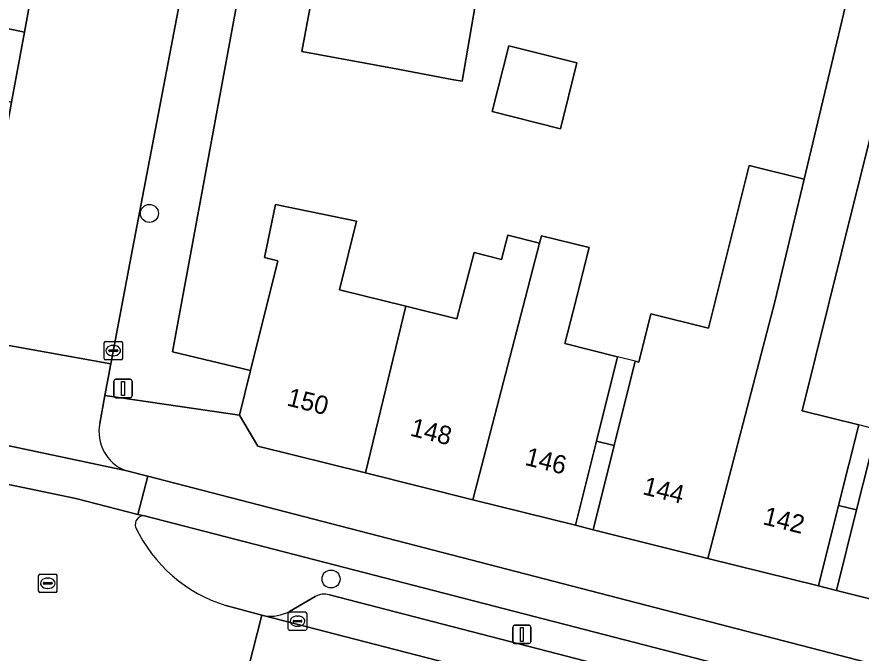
# Model space of a CAD drawing. Extents: x 158086 to 159499, y 382904 to 383981.
# Drawn here: x 158551.81 to 158597.73, y 383159.46 to 383194.06 of the extents above; entities that cross this region are included whole.
import ezdxf

# ---------------------------------------------------------------- set-up
doc = ezdxf.new("R2010")
doc.units = 0
for name, color, linetype in [('IMGEO_Berm_open', 7, 'Continuous'), ('IMGEO_Boom', 7, 'Continuous'), ('IMGEO_Erf', 7, 'Continuous'), ('IMGEO_Fietspad_gesloten', 7, 'Continuous'), ('IMGEO_Fietspad_open', 7, 'Continuous'), ('IMGEO_Kolk', 7, 'Continuous'), ('IMGEO_Lichtmast', 7, 'Continuous'), ('IMGEO_Pand', 7, 'Continuous'), ('IMGEO_Pand_nummerreeks', 7, 'Continuous'), ('IMGEO_Pand_overbouw', 7, 'Continuous'), ('IMGEO_Parkeervlak_open', 7, 'Continuous'), ('IMGEO_Rijbaan_lokaal_gesloten', 7, 'Continuous'), ('IMGEO_Rijbaan_lokaal_open', 7, 'Continuous'), ('IMGEO_Rioolput', 7, 'Continuous'), ('IMGEO_Voetpad_open', 7, 'Continuous')]:
    doc.layers.add(name, color=color, linetype=linetype)

msp = doc.modelspace()

# ---------------------------------------------------------------- linework, layer by layer
at = {"layer": 'IMGEO_Berm_open'}
for points in [[(158568.805, 383162.636), (158600.755, 383154.37), (158601.134, 383155.975), (158558.744, 383166.932)], [(158566.642, 383161.727), (158568.037, 383162.537)], [(158563.175, 383162.055), (158565.129, 383161.526), (158565.27, 383161.488)]]:
    msp.add_lwpolyline(points, dxfattribs=at)
for centre, radius, start, end in [((158558.725, 383166.449), 0.484, 87.7765, 196.6779), ((158565.51, 383169.715), 8.008, 205.1629, 253.0474), ((158568.547, 383161.605), 1.062, 75.9745, 118.7161), ((158565.576, 383163.786), 2.319, 262.406, 297.3573)]:
    msp.add_arc(centre, radius, start, end, dxfattribs=at)
at = {"layer": 'IMGEO_Boom'}
for centre in [(158559.016, 383183.371), (158568.892, 383163.49)]:
    msp.add_circle(centre, 0.489, dxfattribs=at)
at = {"layer": 'IMGEO_Erf'}
for points in [[(158565.715, 383205.279), (158560.261, 383175.849), (158564.517, 383174.829), (158566.003, 383180.788), (158565.282, 383180.967), (158565.879, 383183.857), (158570.287, 383182.948), (158569.357, 383179.223), (158572.966, 383178.323), (158575.735, 383177.632), (158576.678, 383181.236), (158578.166, 383180.867), (158578.51, 383182.182), (158580.241, 383181.753), (158580.345, 383182.152), (158582.934, 383181.511), (158582.355, 383179.223), (158582.203, 383178.621), (158581.614, 383176.29), (158584.473, 383175.577), (158583.33, 383170.993), (158582.186, 383166.409), (158583.156, 383166.167), (158584.3, 383170.751), (158585.442, 383175.335), (158585.64, 383175.286), (158586.293, 383177.907), (158589.424, 383177.127), (158591.631, 383185.974), (158594.621, 383185.228), (158598.078, 383199.698)], [(158577.248, 383197.653), (158576.03, 383190.554), (158575.573, 383190.639), (158572.23, 383191.259), (158567.313, 383192.172), (158569.64, 383204.723)], [(158598.475, 383188.502), (158597.409, 383184.23), (158594.518, 383172.64), (158597.596, 383171.872), (158596.503, 383167.492), (158595.411, 383163.111), (158596.391, 383162.867), (158597.483, 383167.248), (158598.575, 383171.628)]]:
    msp.add_lwpolyline(points, dxfattribs=at)
msp.add_lwpolyline([(158582.265, 383191.561), (158581.367, 383187.978), (158577.664, 383188.906), (158578.562, 383192.489)], close=True, dxfattribs=at)
at = {"layer": 'IMGEO_Fietspad_gesloten'}
msp.add_lwpolyline([(158606.029, 383156.879), (158558.933, 383169.076), (158558.379, 383167.006), (158558.744, 383166.932), (158601.134, 383155.975), (158606.023, 383154.711)], dxfattribs=at)
at = {"layer": 'IMGEO_Fietspad_open'}
msp.add_lwpolyline([(158544.263, 383172.235), (158543.819, 383170.193), (158543.946, 383170.167), (158555.02, 383167.876), (158558.379, 383167.006), (158558.933, 383169.076), (158557.705, 383169.396)], close=True, dxfattribs=at)
at = {"layer": 'IMGEO_Kolk'}
for p, q in [((158556.545, 383175.482), (158556.545, 383176.334)), ((158556.62, 383176.408), (158557.472, 383176.408)), ((158557.033, 383176.188), (158557.058, 383176.188)), ((158557.546, 383176.334), (158557.546, 383175.482)), ((158556.804, 383175.902), (158556.804, 383175.914)), ((158557.242, 383175.865), (158556.844, 383175.865)), ((158556.847, 383175.951), (158557.245, 383175.951)), ((158557.056, 383175.628), (158557.031, 383175.628)), ((158557.288, 383175.914), (158557.288, 383175.902)), ((158557.472, 383175.408), (158556.62, 383175.408)), ((158566.57, 383160.771), (158566.57, 383161.623)), ((158566.645, 383161.697), (158567.497, 383161.697)), ((158567.058, 383161.477), (158567.083, 383161.477)), ((158567.571, 383161.623), (158567.571, 383160.771)), ((158566.829, 383161.191), (158566.829, 383161.203)), ((158567.267, 383161.154), (158566.869, 383161.154)), ((158566.872, 383161.24), (158567.27, 383161.24)), ((158567.081, 383160.917), (158567.056, 383160.917)), ((158567.313, 383161.203), (158567.313, 383161.191)), ((158567.497, 383160.697), (158566.645, 383160.697))]:
    msp.add_line(p, q, dxfattribs=at)
for points in [[(158556.545, 383175.482), (158556.545, 383176.334)], [(158556.62, 383176.408), (158557.472, 383176.408)], [(158557.546, 383176.334), (158557.546, 383175.482)], [(158557.472, 383175.408), (158556.62, 383175.408)], [(158566.57, 383160.771), (158566.57, 383161.623)], [(158566.645, 383161.697), (158567.497, 383161.697)], [(158567.571, 383161.623), (158567.571, 383160.771)], [(158567.497, 383160.697), (158566.645, 383160.697)]]:
    msp.add_lwpolyline(points, dxfattribs=at)
for centre, radius, start, end in [((158556.622, 383176.332), 0.0765, 91.552, 178.448), ((158556.622, 383176.332), 0.0765, 91.552, 178.448), ((158557.47, 383176.332), 0.0765, 1.552, 88.448), ((158557.47, 383176.332), 0.0765, 1.552, 88.448), ((158556.844, 383175.911), 0.0403, 85.8775, 175.7526), ((158556.841, 383175.901), 0.0366, 178.938, 274.7102), ((158557.245, 383175.908), 0.043, 264.8664, 352.4533), ((158557.249, 383175.913), 0.0386, 1.7309, 96.639), ((158556.622, 383175.484), 0.0765, 181.552, 268.448), ((158556.622, 383175.484), 0.0765, 181.552, 268.448), ((158557.47, 383175.484), 0.0765, 271.552, 358.448), ((158557.47, 383175.484), 0.0765, 271.552, 358.448), ((158566.647, 383161.621), 0.0765, 91.552, 178.448), ((158566.647, 383161.621), 0.0765, 91.552, 178.448), ((158567.495, 383161.621), 0.0765, 1.552, 88.448), ((158567.495, 383161.621), 0.0765, 1.552, 88.448), ((158566.869, 383161.2), 0.0403, 85.8775, 175.7526), ((158566.866, 383161.19), 0.0366, 178.938, 274.7102), ((158567.27, 383161.197), 0.043, 264.8664, 352.4533), ((158567.274, 383161.202), 0.0386, 1.7309, 96.639), ((158566.647, 383160.773), 0.0765, 181.552, 268.448), ((158566.647, 383160.773), 0.0765, 181.552, 268.448), ((158567.495, 383160.773), 0.0765, 271.552, 358.448), ((158567.495, 383160.773), 0.0765, 271.552, 358.448)]:
    msp.add_arc(centre, radius, start, end, dxfattribs=at)
for centre, major_axis, ratio, start_param, end_param in [((158557.032, 383175.908), (-0.387, 0.002), 0.722429, 4.712389, 7.853982), ((158557.057, 383175.908), (-0.39, 0.002), 0.717154, 1.570796, 4.712389), ((158567.057, 383161.197), (-0.387, 0.002), 0.722429, 4.712389, 7.853982), ((158567.082, 383161.197), (-0.39, 0.002), 0.717154, 1.570796, 4.712389)]:
    msp.add_ellipse(centre, major_axis=major_axis, ratio=ratio, start_param=start_param, end_param=end_param, dxfattribs=at)
at = {"layer": 'IMGEO_Lichtmast'}
for p, q in [((158557.083, 383173.449), (158557.083, 383174.249)), ((158557.083, 383174.249), (158557.083, 383173.449)), ((158557.183, 383174.349), (158557.973, 383174.349)), ((158557.973, 383174.349), (158557.183, 383174.349)), ((158558.073, 383174.249), (158558.073, 383173.449)), ((158558.073, 383173.449), (158558.073, 383174.249)), ((158557.973, 383173.349), (158557.183, 383173.349)), ((158557.183, 383173.349), (158557.973, 383173.349)), ((158578.773, 383160.075), (158578.773, 383160.875)), ((158578.773, 383160.875), (158578.773, 383160.075)), ((158578.873, 383160.975), (158579.663, 383160.975)), ((158579.663, 383160.975), (158578.873, 383160.975)), ((158579.763, 383160.875), (158579.763, 383160.075)), ((158579.763, 383160.075), (158579.763, 383160.875)), ((158579.663, 383159.975), (158578.873, 383159.975)), ((158578.873, 383159.975), (158579.663, 383159.975))]:
    msp.add_line(p, q, dxfattribs=at)
for points in [[(158557.503, 383174.224), (158557.653, 383174.224), (158557.653, 383173.474), (158557.503, 383173.474), (158557.503, 383174.224)], [(158579.193, 383160.85), (158579.343, 383160.85), (158579.343, 383160.1), (158579.193, 383160.1), (158579.193, 383160.85)]]:
    msp.add_lwpolyline(points, dxfattribs=at)
for centre, start, end in [((158557.183, 383174.249), 90, 180), ((158557.183, 383174.249), 90, 180), ((158557.973, 383174.249), 0, 90), ((158557.973, 383174.249), 360, 90), ((158557.183, 383173.449), 180, 270), ((158557.183, 383173.449), 180, 270), ((158557.973, 383173.449), 270, 0), ((158557.973, 383173.449), 270, 0), ((158578.873, 383160.875), 90, 180), ((158578.873, 383160.875), 90, 180), ((158579.663, 383160.875), 0, 90), ((158579.663, 383160.875), 360, 90), ((158578.873, 383160.075), 180, 270), ((158578.873, 383160.075), 180, 270), ((158579.663, 383160.075), 270, 0), ((158579.663, 383160.075), 270, 0)]:
    msp.add_arc(centre, 0.1, start, end, dxfattribs=at)
at = {"layer": 'IMGEO_Pand'}
for points in [[(158579.6, 383202.881), (158578.312, 383203.119), (158576.895, 383203.382), (158577.637, 383207.406), (158572.978, 383208.266), (158572.236, 383204.244), (158569.64, 383204.723), (158567.313, 383192.172), (158572.23, 383191.259), (158575.573, 383190.639), (158576.03, 383190.554), (158577.248, 383197.653), (158578.661, 383197.411)], [(158597.596, 383171.872), (158594.518, 383172.64), (158597.409, 383184.23), (158598.475, 383188.502), (158599.547, 383192.802), (158600.319, 383195.897), (158609.12, 383194.452), (158609.69, 383197.759), (158600.842, 383199.263), (158598.078, 383199.698), (158594.621, 383185.228), (158593.027, 383178.559), (158589.397, 383164.611), (158595.411, 383163.111), (158596.503, 383167.492)], [(158582.265, 383191.561), (158578.562, 383192.489), (158577.664, 383188.906), (158581.367, 383187.978)], [(158594.621, 383185.228), (158591.631, 383185.974), (158589.424, 383177.127), (158586.293, 383177.907), (158585.64, 383175.286), (158585.442, 383175.335), (158584.3, 383170.751), (158583.156, 383166.167), (158589.397, 383164.611), (158593.027, 383178.559)], [(158570.766, 383169.256), (158572.966, 383178.323), (158569.357, 383179.223), (158570.287, 383182.948), (158565.879, 383183.857), (158565.282, 383180.967), (158566.003, 383180.788), (158564.517, 383174.829), (158563.909, 383172.391), (158564.916, 383170.715)], [(158579.457, 383178.739), (158579.75, 383179.867), (158580.241, 383181.753), (158578.51, 383182.182), (158578.166, 383180.867), (158576.678, 383181.236), (158575.735, 383177.632), (158572.966, 383178.323), (158570.766, 383169.256), (158576.609, 383167.8)], [(158584.473, 383175.577), (158581.614, 383176.29), (158582.203, 383178.621), (158582.355, 383179.223), (158582.934, 383181.511), (158580.345, 383182.152), (158580.241, 383181.753), (158579.75, 383179.867), (158579.457, 383178.739), (158576.609, 383167.8), (158582.186, 383166.409), (158583.33, 383170.993)], [(158598.575, 383171.628), (158597.483, 383167.248), (158596.391, 383162.867), (158602.794, 383161.27), (158607.464, 383179.997), (158604.536, 383180.787), (158602.56, 383172.861), (158599.097, 383173.724)]]:
    msp.add_lwpolyline(points, close=True, dxfattribs=at)
at = {"layer": 'IMGEO_Pand_overbouw'}
for points in [[(158585.442, 383175.335), (158584.473, 383175.577), (158583.33, 383170.993), (158584.3, 383170.751)], [(158598.575, 383171.628), (158597.596, 383171.872), (158596.503, 383167.492), (158597.483, 383167.248)], [(158584.3, 383170.751), (158583.33, 383170.993), (158582.186, 383166.409), (158583.156, 383166.167)], [(158597.483, 383167.248), (158596.503, 383167.492), (158595.411, 383163.111), (158596.391, 383162.867)]]:
    msp.add_lwpolyline(points, close=True, dxfattribs=at)
at = {"layer": 'IMGEO_Parkeervlak_open'}
for points in [[(158568.037, 383162.537), (158566.642, 383161.727)], [(158608.815, 383152.301), (158605.622, 383153.113), (158600.755, 383154.37), (158568.805, 383162.636)], [(158565.27, 383161.488), (158603.182, 383151.697)]]:
    msp.add_lwpolyline(points, dxfattribs=at)
for centre, radius, start, end in [((158568.547, 383161.605), 1.062, 75.9745, 118.7161), ((158565.576, 383163.786), 2.319, 262.406, 297.3573)]:
    msp.add_arc(centre, radius, start, end, dxfattribs=at)
at = {"layer": 'IMGEO_Rijbaan_lokaal_gesloten'}
msp.add_lwpolyline([(158603.182, 383151.697), (158565.27, 383161.488), (158565.129, 383161.526), (158563.65, 383155.688), (158604.482, 383145.118), (158607.068, 383144.465)], dxfattribs=at)
at = {"layer": 'IMGEO_Rijbaan_lokaal_open'}
msp.add_lwpolyline([(158556.908, 383175.192), (158557.957, 383180.662), (158561.882, 383201.268), (158562.527, 383204.741), (158564.32, 383214.398), (158564.956, 383217.826), (158565.739, 383222.043), (158567.556, 383233.332), (158559.7, 383234.689), (158559.687, 383234.543), (158557.269, 383221.447), (158556.732, 383218.49), (158553.538, 383200.506), (158552.215, 383193.232), (158551.52, 383189.415), (158551.464, 383189.107), (158550.099, 383181.832), (158549.132, 383176.584)], close=True, dxfattribs=at)
for points in [[(158556.908, 383175.192), (158549.132, 383176.584)], [(158556.592, 383173.462), (158556.908, 383175.192)], [(158556.317, 383171.955), (158556.592, 383173.462)], [(158544.263, 383172.235), (158557.705, 383169.396)], [(158558.744, 383166.932), (158558.379, 383167.006), (158555.02, 383167.876), (158543.946, 383170.167), (158543.819, 383170.193), (158543.338, 383170.287)], [(158536.291, 383168.021), (158535.351, 383168.176), (158533.969, 383162.299), (158541.816, 383160.671), (158542.185, 383160.577), (158547.656, 383159.441), (158553.425, 383158.16), (158554.123, 383157.994), (158560.097, 383156.536), (158560.501, 383156.444), (158563.65, 383155.688), (158565.129, 383161.526), (158563.175, 383162.055)]]:
    msp.add_lwpolyline(points, dxfattribs=at)
for centre, radius, start, end in [((158558.517, 383171.492), 2.248, 168.1168, 248.834), ((158558.725, 383166.449), 0.484, 87.7765, 196.6779), ((158565.51, 383169.715), 8.008, 205.1629, 253.0474)]:
    msp.add_arc(centre, radius, start, end, dxfattribs=at)
at = {"layer": 'IMGEO_Rioolput'}
for p, q in [((158552.986, 383162.833), (158552.986, 383163.685)), ((158553.061, 383163.759), (158553.913, 383163.759)), ((158553.987, 383163.685), (158553.987, 383162.833)), ((158553.245, 383163.253), (158553.245, 383163.265)), ((158553.683, 383163.216), (158553.285, 383163.216)), ((158553.288, 383163.302), (158553.686, 383163.302)), ((158553.474, 383163.539), (158553.499, 383163.539)), ((158553.729, 383163.265), (158553.729, 383163.253)), ((158553.913, 383162.759), (158553.061, 383162.759)), ((158553.497, 383162.979), (158553.472, 383162.979))]:
    msp.add_line(p, q, dxfattribs=at)
for points in [[(158552.986, 383162.833), (158552.986, 383163.685)], [(158553.061, 383163.759), (158553.913, 383163.759)], [(158553.987, 383163.685), (158553.987, 383162.833)], [(158553.913, 383162.759), (158553.061, 383162.759)]]:
    msp.add_lwpolyline(points, dxfattribs=at)
for centre, radius, start, end in [((158553.063, 383163.683), 0.0765, 91.552, 178.448), ((158553.063, 383163.683), 0.0765, 91.552, 178.448), ((158553.911, 383163.683), 0.0765, 1.552, 88.448), ((158553.911, 383163.683), 0.0765, 1.552, 88.448), ((158553.285, 383163.262), 0.0403, 85.8775, 175.7526), ((158553.282, 383163.252), 0.0366, 178.938, 274.7102), ((158553.686, 383163.259), 0.043, 264.8664, 352.4533), ((158553.69, 383163.264), 0.0386, 1.7309, 96.639), ((158553.063, 383162.835), 0.0765, 181.552, 268.448), ((158553.063, 383162.835), 0.0765, 181.552, 268.448), ((158553.911, 383162.835), 0.0765, 271.552, 358.448), ((158553.911, 383162.835), 0.0765, 271.552, 358.448)]:
    msp.add_arc(centre, radius, start, end, dxfattribs=at)
for centre, major_axis, ratio, start_param, end_param in [((158553.473, 383163.259), (-0.387, 0.002), 0.722429, 4.712389, 7.853982), ((158553.498, 383163.259), (-0.39, 0.002), 0.717154, 1.570796, 4.712389)]:
    msp.add_ellipse(centre, major_axis=major_axis, ratio=ratio, start_param=start_param, end_param=end_param, dxfattribs=at)
at = {"layer": 'IMGEO_Voetpad_open'}
for points in [[(158573.515, 383250), (158584.576, 383309.191), (158581.664, 383309.815), (158579.736, 383299.401), (158570.635, 383250), (158570.464, 383249.119), (158567.556, 383233.332), (158565.739, 383222.043), (158564.956, 383217.826), (158565.977, 383217.63), (158565.341, 383214.202), (158564.32, 383214.398), (158562.527, 383204.741), (158563.55, 383204.551), (158562.905, 383201.078), (158561.882, 383201.268), (158557.957, 383180.662), (158556.908, 383175.192), (158556.592, 383173.462), (158563.909, 383172.391), (158564.517, 383174.829), (158560.261, 383175.849), (158565.715, 383205.279), (158565.366, 383205.337)], [(158552.215, 383193.232), (158551.278, 383193.422), (158550.537, 383189.593), (158551.52, 383189.415)]]:
    msp.add_lwpolyline(points, close=True, dxfattribs=at)
for points in [[(158548.931, 383175.46), (158549.132, 383176.584), (158550.099, 383181.832), (158551.464, 383189.107), (158551.52, 383189.415), (158550.537, 383189.593), (158551.278, 383193.422), (158552.215, 383193.232), (158553.538, 383200.506), (158556.732, 383218.49)], [(158596.391, 383162.867), (158595.411, 383163.111), (158589.397, 383164.611), (158583.156, 383166.167), (158582.186, 383166.409), (158576.609, 383167.8), (158570.766, 383169.256), (158564.916, 383170.715), (158563.909, 383172.391), (158556.592, 383173.462), (158556.317, 383171.955)], [(158557.705, 383169.396), (158558.933, 383169.076), (158606.029, 383156.879)], [(158610.416, 383159.48), (158607.55, 383160.169), (158602.794, 383161.27), (158596.391, 383162.867)]]:
    msp.add_lwpolyline(points, dxfattribs=at)
msp.add_arc((158558.517, 383171.492), 2.248, 168.1168, 248.834, dxfattribs=at)

# ---------------------------------------------------------------- texts
at = {"layer": 'IMGEO_Pand_nummerreeks'}
for s, rotation, p in [('150', 345.9997, (158566.439, 383172.933)), ('148', 345.9969, (158573.148, 383171.293)), ('146', 345.9969, (158579.388, 383169.703)), ('144', 345.9969, (158585.79, 383168.107)), ('142', 345.9969, (158592.334, 383166.475))]:
    msp.add_text(s, height=1, rotation=rotation, dxfattribs=at).set_placement(p)

doc.saveas('drawing.dxf')
